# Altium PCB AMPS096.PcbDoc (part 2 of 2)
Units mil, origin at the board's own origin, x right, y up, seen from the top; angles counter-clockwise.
Board outline 2170 x 3820 mil, 2 copper layers (Top Layer, Bottom Layer), stack 62 mil thick; 82 components, 27 nets, 181 pads, 486 vias.
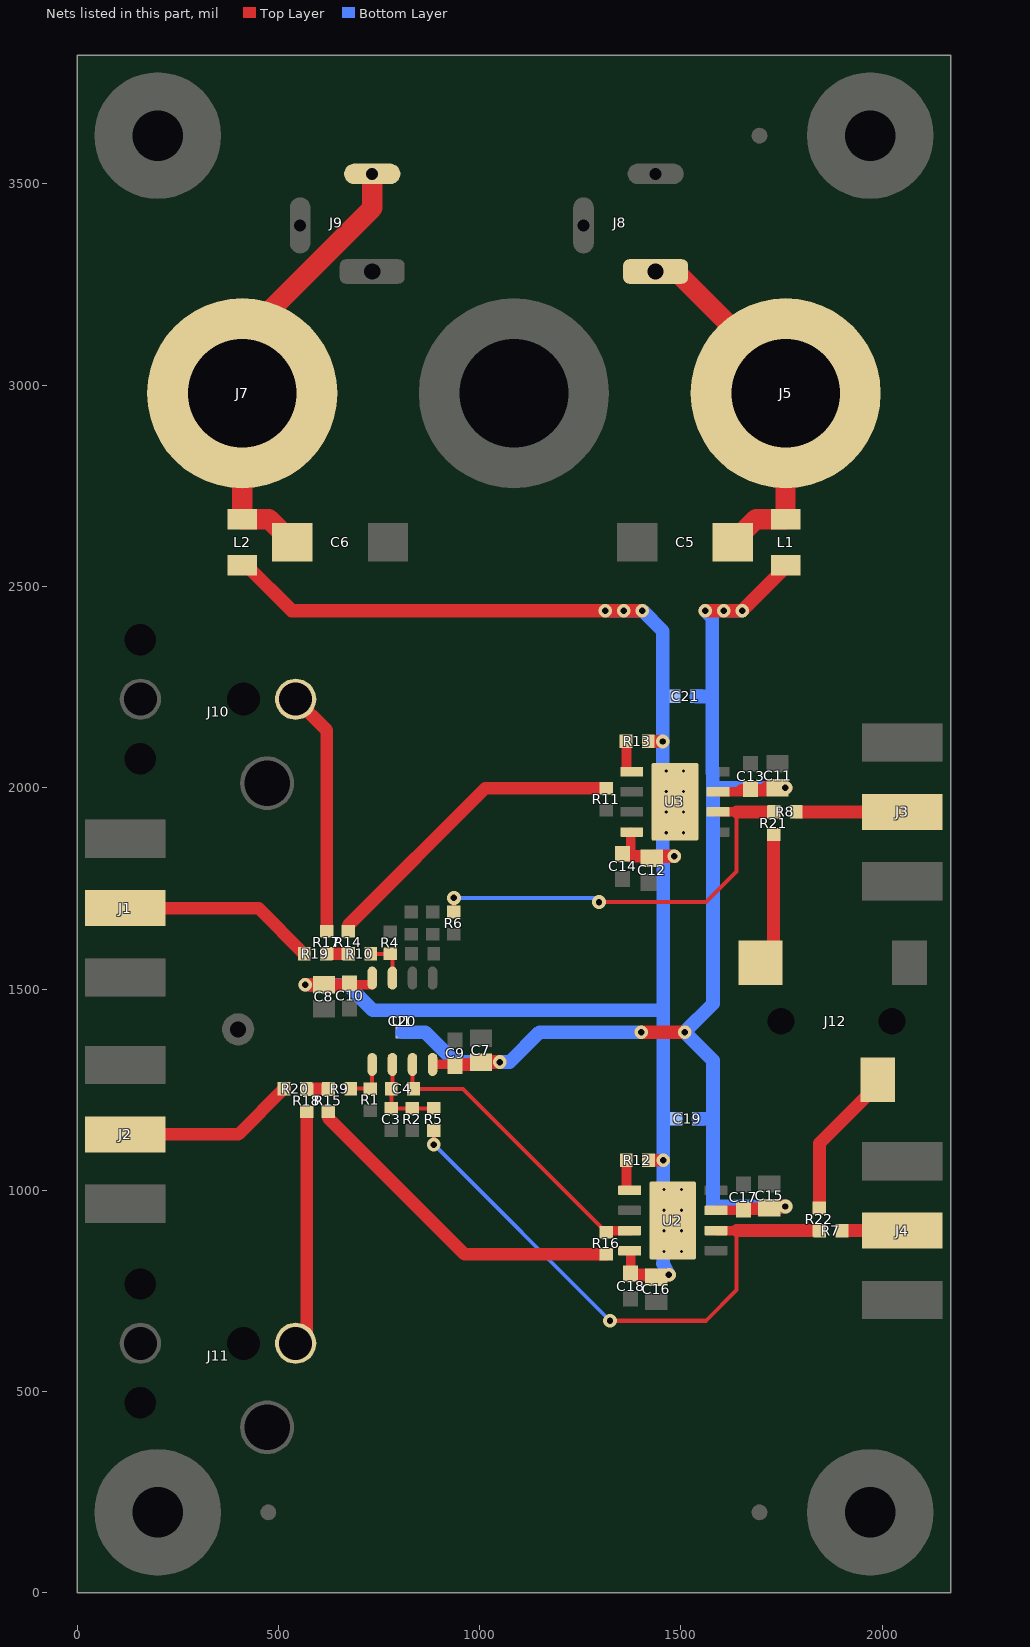
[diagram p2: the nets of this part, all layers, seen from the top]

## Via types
v1: diameter 34, hole 16, Top Layer to Bottom Layer, tented both sides, 470 vias
v2: diameter 19.68, hole 7.87, Top Layer to Bottom Layer, tented both sides, 8 vias
v3: diameter 19.68, hole 7.87, Top Layer to Bottom Layer, 8 vias

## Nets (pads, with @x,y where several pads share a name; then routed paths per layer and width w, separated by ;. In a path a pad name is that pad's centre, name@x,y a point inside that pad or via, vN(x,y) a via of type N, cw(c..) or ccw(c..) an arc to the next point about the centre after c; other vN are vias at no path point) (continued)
NetC3_1: C3.1 C4.1 R2.2 R5.1 U1.6 | length 215.8
  Top Layer w10: U1.6@783,1312.72 783,1254.56 C4.1@780.44,1252 C3.1@780.44,1203.56 R5.1@886,1203.56
NetC4_2: C4.2 R16.2 U1.7 U2.3 | length 750
  Top Layer w10: U1.7@833,1312.72 833,1254.56 C4.2@835.56,1252 958.06,1252 R16.2@1314,896.06
  Top Layer w23.62: R16.2@1314,896.06 1317.94,900 U2.3@1374.72,900
NetC5_1: C5.1 J5.1 J8.1 L1.1 | length 933.3
  Top Layer w50: J8.1@1437,3282.43 1487.57,3282.43 1760,3010 J5.1@1760,2980 L1.1@1760,2667.09 1686.18,2667.09 C5.1@1629.09,2610
NetC6_2: C6.2 J7.1 J9.2 L2.1 | length 1139.2
  Top Layer w50: C6.2@533.94,2610 476.85,2667.09 L2.1@410,2667.09 J7.1@410,2980 410,3117 733,3440 J9.2@733,3524.95
NetJ1_1: J1.1 R19.2 | length 491
  Top Layer w31.5: J1.1@120,1701 450.41,1701 R19.2@563.97,1587.44
NetJ2_1: J2.1 R20.2 | length 441
  Top Layer w31.5: J2.1@120,1139 400.41,1139 R20.2@513.97,1252.56
NetJ3_1: J3.1 R8.1 | length 264
  Top Layer w31.5: R8.1@1786.03,1940 J3.1@2050,1940
NetJ4_1: J4.1 R7.1 | length 150
  Top Layer w31.5: R7.1@1900.03,900 J4.1@2050,900
NetJ10_3: J10.3 R17.1 | length 608.5
  Top Layer w31.5: J10.3@542.83,2220 620,2142.83 R17.1@620,1643.47
NetJ11_3: J11.3 R18.2 | length 586.2
  Top Layer w31.5: J11.3@542.83,620 570,647.17 R18.2@570,1194.97
NetJ12_2: J12.2 R21.2 | length 323.5
  Top Layer w31.5: J12.2@1697.56,1565.67 J12.2@1710,1578.11 ; J12.2@1730,1578.11 R21.2@1730,1883.97
NetJ12_3: J12.3 R22.1 | length 378.3
  Top Layer w31.5: R22.1@1844,956.03 1844,1117 1988.9,1261.9 J12.3@1988.9,1274.33
NetR1_2: R1.2 R9.1 U1.5 | length 110.7
  Top Layer w10: R9.1@679.56,1252.56 R1.2@728,1252.56 733,1257.56 U1.5@733,1312.72
NetR4_1: R4.1 R10.1 U1.3 | length 110.7
  Top Layer w10: R10.1@729.56,1587.44 R4.1@778,1587.44 783,1582.44 U1.3@783,1527.28
NetR5_2: R5.2 R7.2 R22.2 U2.6 | length 1392.4
  Top Layer w10: v1(886,1113.72) R5.2@886,1148.44 ; v1(1323.72,676.01) 1562.16,676.01 1638.15,752 1638.15,900
  Top Layer w23.62: U2.6@1589.28,900 1638.15,900
  Top Layer w31.5: 1638.15,900 R7.2@1834,900
  Bottom Layer w10: v1(886,1113.72) v1(1323.72,676.01)
NetR6_2: R6.2 R8.2 R21.1 U3.6 | length 1061.3
  Top Layer w10: R6.2@936,1691.56 v1(936,1726.28) ; v1(1296.27,1716.01) 1562.16,1716.01 1638.15,1792 1638.15,1940
  Top Layer w23.62: U3.6@1589.28,1940 1638.15,1940
  Top Layer w31.5: 1638.15,1940 R8.2@1730,1940
  Bottom Layer w10: v1(936,1726.28) 1286,1726.28 v1(1296.27,1716.01)
NetR9_2: R9.2 R15.2 R18.1 R20.1 | length 55.4
  Top Layer w31.5: R20.1@569.09,1252.56 R9.2@624.44,1252.56
NetR10_2: R10.2 R14.2 R17.2 R19.1 | length 55.4
  Top Layer w31.5: R19.1@619.09,1587.44 R10.2@674.44,1587.44
NetR11_1: R11.1 R14.1 | length 796.6
  Top Layer w31.5: R14.1@673.53,1643.47 673.53,1658.53 1014.06,1999.06 R11.1@1314,1999.06
NetR12_2: R12.2 U2.1 | length 63
  Top Layer w10: U2.1@1365.17,1009.55 U2.1@1374.72,1000
  Top Layer w25: U2.1@1365.17,1009.55 R12.2@1365.17,1059
NetR13_2: R13.2 U3.1 | length 63
  Top Layer w10: U3.1@1365.17,2049.55 U3.1@1374.72,2040
  Top Layer w25: U3.1@1365.17,2049.55 R13.2@1365.17,2099
NetR15_1: R15.1 R16.1 | length 845.7
  Top Layer w31.5: R15.1@623.53,1194.97 623.53,1180.35 962.94,840.94 R16.1@1314,840.94
VS+: C7.1 C9.1 C11.1 C13.1 C15.1 C17.1 C19.1 C20.1 C21.1 L1.2 U1.8 U2.7 U3.7 | length 3599
  Top Layer w23.62: U1.8@883,1312.72 C9.1@939,1312.72 ; U2.7@1589.28,950 1646.06,950 C17.1@1650,953.94 ; U3.7@1589.28,1990 1646.06,1990 1650,1993.94
  Top Layer w31.5: C9.1@939,1312.72 996.09,1312.72 C7.1@1002,1318.62 ; C17.1@1650,953.94 1707.09,953.94 C15.1@1713,959.84 ; 1650,1993.94 1707.09,1993.94 C11.1@1713,1999.84
  Top Layer w34: C7.1@1003,1318.62 v1(1049.53,1318.62) ; v1(1401,1393) v1(1509,1393) ; v1(1560,2440) v1(1606,2440) v1(1651.91,2440) ; v1@1652.09,2440 L1.2@1760,2547.91 ; C15.1@1713,959.84 v1(1759.53,959.84) ; C11.1@1713,1999.84 v1(1759.53,1999.84)
  Bottom Layer w34: C20.1@808,1393 864.25,1393 938.63,1318.62 v1(1049.53,1318.62) 1074.42,1318.62 1148.8,1393 v1(1401,1393) ; C21.1@1538.47,2226.92 1575.37,2226.92 1577.29,2225 ; C19.1@1542.56,1177.76 1577.26,1177.76 1579.5,1180 ; v1(1651.91,2440) v1(1606,2440) v1(1560,2440) 1577.29,2422.71 1577.29,2225 ; v1(1759.53,959.84) 1579.5,959.84 1579.5,1180 ; v1(1759.53,1999.84) 1579.5,1999.84 ; 1577.29,2225 1577.29,2068.13 1579.5,1999.84 ; 1579.5,1180 1579.5,1322.5 v1(1509,1393) 1579.5,1463.5 1579.5,1999.84
VS-: C8.1 C10.1 C12.1 C14.1 C16.1 C18.1 C19.2 C20.2 C21.2 L2.2 R12.1 R13.1 U1.4 U2.4 U2.9@1479.73,925 U3.4 U3.9@1484.95,1965 | length 4287.5
  Top Layer w23.62: C10.1@677,1510.55 U1.4@733,1510.55 ; C18.1@1374.72,789.56 U2.4@1374.72,850 ; 1374.72,1829.56 U3.4@1374.72,1890
  Top Layer w31.5: C8.1@613,1510.55 C10.1@677,1510.55 ; C18.1@1374.72,789.56 C16.1@1437,789.56 ; 1374.72,1829.56 C12.1@1437,1829.56 ; R12.1@1419.74,1075 v1(1456.03,1075) ; 1436.28,2115 v1(1455,2115)
  Top Layer w34: L2.2@420,2552.91 532.91,2440 v1(1404,2440) ; v1(566.47,1510.55) C8.1@613,1510.55 ; C12.1@1437,1829.56 v1(1483.53,1829.56) ; C16.1@1438.58,783.59 v1(1470.08,790)
  Bottom Layer w34: v1(566.47,1510.55) 671.2,1510.55 734.75,1447 808,1447 1455,1447 ; v1(1312.09,2440) v1(1358,2440) v1(1404,2440) 1455,2389 1455,2099 1455,1829.56 ; v1(1470.08,790) 1455,818.09 1456.03,819.12 v1(1456.03,1075) 1456.03,1828.53 1455,1829.56 ; v1(1483.53,1829.56) 1455,1829.56
  other v2: 1458.08,848.23 1501.39,848.23 1458.08,1001.77 1501.39,1001.77 1463.3,1888.23 1506.61,1888.23 1463.3,2041.77 1506.61,2041.77
  other v3: 1458.08,899.41 1501.39,899.41 1458.08,950.59 1501.39,950.59 1463.3,1939.41 1506.61,1939.41 1463.3,1990.59 1506.61,1990.59
pads on no net: FID1.1 FID2.1 FID3.1 FID4.1 FID5.1 FID6.1 H5.0 H6.0 H7.0 H8.0 J8.3 J9.3 J10.4 J10.M1 J10.M2 J10.M3 J11.4 J11.M1 J11.M2 J11.M3 J12.4 J12.5 U2.2 U2.5 U2.8 U2.9@1479.73,925 U3.2 U3.5 U3.8 U3.9@1484.95,1965

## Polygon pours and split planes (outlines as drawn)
GND on Top Layer "TOP_LAYER_GND_P006" (solid, remove dead copper, pour order 6): 25,3795 2145,3795 2145,25 25,25
VS- on Bottom Layer "BOTTOM_LAYER_VS-_P020" (solid, remove dead copper, pour order 20): 1420,2061.68 1424.95,2056.72 1424.95,1868.68 1545,1868.68 1545,2061.68
GND on Bottom Layer "BOTTOM_LAYER_GND_P016" (solid, remove dead copper, pour order 16): 30,3790 25.49,3785.49 25.49,25.49 2144.51,25.49 2144.51,3794.51 25.49,3794.51 25,3795
VS- on Bottom Layer "BOTTOM_LAYER_VS-_P014" (solid, remove dead copper, pour order 14): 1419.73,1021.68 1419.73,828.68 1535,828.68 1535,1021.68

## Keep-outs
Keep-Out Layer:
  text ".Layer_Name" at 567,-858.49 h60

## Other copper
Top Layer:
  text ".Layer_Name" at 567,-858.49 h60
Bottom Layer:
  text ".Layer_Name" at 567,-858.49 h60

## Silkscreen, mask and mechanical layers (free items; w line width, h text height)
Top Overlay:
  text "Warning" at 965,3735 h72.83
  text "Connectors" at 925,3640 h72.83
  text "are positive" at 920,3540 h72.83
  text "tip" at 1050,3435 h72.83
  text "'.PRJ_Number'.PCB_Rev" at 688.05,331 h40
  text "BUF634ADDAEVM" at 1133.97,330 h72.83
  text ".Layer_Name" at 567,-858.49 h60
Bottom Overlay:
  text ".Layer_Name" at 567,-858.49 h60
Top Paste:
  text ".Layer_Name" at 567,-858.49 h60
Bottom Paste:
  text ".Layer_Name" at 567,-858.49 h60
Top Solder:
  text ".Layer_Name" at 567,-858.49 h60
  text ".Layer_Name" at 567,-858.49 h60
Bottom Solder:
  text ".Layer_Name" at 567,-858.49 h60
Drill Guide:
  text ".Layer_Name" at 567,-858.49 h60
M1 Board Outline:
  the board outline again, w10
  text ".Layer_Name" at 567,-858.49 h60
M2 Board Dimensions:
  rectangle: -10,-265 115,-140
  rectangle: 115,-390 490,-265
  lines w7: -10,-265 990,-265 ; 115,-390 115,-140 ; 240,-390 240,-140 ; 490,-390 490,-140 ; 740,-390 740,-140 ; -10,-390 990,-390 990,-140 -10,-140 -10,-390
  text ".Layer_Name" at 567,-858.49 h60
M3 3D STEP Top:
  text ".Layer_Name" at 567,-858.49 h60
M4 3D STEP Bottom:
  text ".Layer_Name" at 567,-858.49 h60
M5 Assembly Top:
  lines w10: -302,-930.17 6298,-930.17 ; -302,-726.83 6300,-726.83 ; -302,-523.5 -302,-1133.5 3703,-1133.5 6300,-1133.5 6300,-523.5 -301.5,-523.5 -301.5,-1133.5 1274,-1133.5 ; 2163,-1133.5 2163,-523.5 ; 3430,-726.83 3430,-523.5 ; 4270,-726.83 4270,-523.5 ; 4892,-1140 4892,-937.17
  text "COMPONENTS MARKED 'DNP' SHOULD NOT BE POPULATED." at 1143.5,-318.5 h60
  text "ASSEMBLY VARIANT:" at 1143,-434 h60
  text ".VariantName" at 2179,-434 h60
  text "BUF634ADEVM" at 2737,-649 h60
  text "PCB VIEWED FROM TOP SIDE" at -238.5,-655.67 h60
  text "BOARD #:" at 2238,-655.67 h60
  text "REV:" at 3628,-655.67 h60
  text ".PCB_Rev" at 3919.5,-655.67 h60
  text "SVN REV:" at 4466,-655.67 h60
  text ".VersionControl_RevNumber" at 4972,-655.67 h60
  text "TID #:" at 2238,-859 h60
  text ".TID" at 2783.5,-859 h60
  text "PLOT NAME =" at -238.5,-1064.34 h60
  text ".plot_File_Name" at 567,-1064.34 h60
  text "GENERATED    :" at 2240,-1064.34 h60
  text ".Print_Date" at 3109.5,-1064.34 h60
  text ".Print_Time" at 3838.5,-1064.34 h60
  text "TEXAS INSTRUMENTS" at 5103,-1064.34 h60
M6 Assembly Bottom:
  lines w10: -302.5,-727.33 6299.5,-727.33 ; -300.5,-930.67 6299.5,-930.67 ; 1105.5,-1140.5 1105.5,-937.67 ; 1727.5,-727.33 1727.5,-524 ; 2567.5,-727.33 2567.5,-524 ; 3834.5,-1134 3834.5,-524 ; 4723.5,-1134 6299,-1134 6299,-524 -302.5,-524 -302.5,-1134 2294.5,-1134 6299.5,-1134 6299.5,-524
  text "COMPONENTS MARKED 'DNP' SHOULD NOT BE POPULATED." at 6092,-318 h60
  text ".VariantName" at 5048,-434 h60
  text "ASSEMBLY VARIANT:" at 6087,-434 h60
  text ".VersionControl_RevNumber" at 1025.5,-656.17 h60
  text "SVN REV:" at 1531.5,-656.17 h60
  text ".PCB_Rev" at 2078,-656.17 h60
  text "REV:" at 2369.5,-656.17 h60
  text ".PRJ_Number" at 3214,-656.17 h60
  text "BOARD #:" at 3759.5,-656.17 h60
  text "PCB VIEWED FROM BOTTOM SIDE" at 6236,-656.17 h60
  text ".TID" at 3214,-859.5 h60
  text "TID #:" at 3759.5,-859.5 h60
  text "TEXAS INSTRUMENTS" at 894.5,-1064.84 h60
  text ".Print_Time" at 2159,-1064.84 h60
  text ".Print_Date" at 2888,-1064.84 h60
  text "GENERATED    :" at 3757.5,-1064.84 h60
  text ".plot_File_Name" at 5430.5,-1064.84 h60
  text "PLOT NAME =" at 6236,-1064.84 h60
M9 Title Sheet:
  drawing of 57 lines, arcs and shapes, not listed
  text "1" at 729.84,8036.5 h70
  text "2" at 3225.5,8036.5 h70
  text "3" at 5714.84,8036.5 h70
  text "4" at 8221.51,8036.5 h70
  text "5" at 10720.5,8036.5 h70
  text "6" at 13225.5,8036.5 h70
  text "A" at -426.5,6893.5 h70
  text "A" at 14373.5,6893.5 h70
  text "B" at -426.5,4513.5 h70
  text "B" at 14373.5,4513.5 h70
  text "C" at -426.5,2138.5 h70
  text "C" at 14373.5,2138.5 h70
  text "PROJECT TITLE:" at 11333.5,277.5 h45
  text ".PRJ_Title" at 11383.5,144.17 h70
  text "DESIGNED FOR:" at 11333.5,-23.5 h45
  text ".PRJ_Customer" at 11383.5,-163.5 h70
  text "D" at -426.5,-231.5 h70
  text "D" at 14373.5,-231.5 h70
  text "FILE NAME:" at 11333.5,-323.5 h45
  text ".PCB_File_Name_No_Path" at 11383.5,-443.5 h70
  text "Texas Instruments (TI) and/or its licensors do not warrant the accuracy or completeness of this specification" at 6364,-605.34 h45
  text "ENGINEER:" at 11333.5,-613.5 h45
  text "LAYOUT BY:" at 12838.5,-613.5 h45
  text "or any information contained therein. TI and/or its licensors do not warrant that this design will meet" at 6319.01,-718 h45
  text "Sean Cashin" at 11383.5,-768.49 h70
  text "Sean Cashin" at 12889,-768.49 h70
  text "the specifications, will be suitable for your application or fit for any particular purpose, or will operate in" at 6319.01,-830.67 h45
  text ".Layer_Name" at 567,-858.49 h60
  text "ALTIUM DESIGNER VERSION:" at 12838.5,-923.5 h45
  text "an implementation. TI and/or its licensors do not warrant that the design is production worthy. You should" at 6319.01,-943.33 h45
  text "completely validate and test your design implementation to confirm the system functionality for your application." at 6364,-1056 h45
  text ".print_Scale" at 11383.5,-1056.83 h70
  text ".Application_BuildNumber" at 12889,-1056.83 h70
  text "1" at 729.84,-1263.5 h70
  text "2" at 3225.5,-1263.5 h70
  text "3" at 5714.84,-1263.5 h70
  text "4" at 8221.51,-1263.5 h70
  text "5" at 10720.5,-1263.5 h70
  text "6" at 13225.5,-1263.5 h70
M10 Fab Notes:
  drawing of 189 lines, arcs and shapes, not listed
  text "DESIGN INFORMATION" at 12382.02,6356.17 h60
  text "MIN. TRACK WIDTH:" at 11737.46,6224.05 h60
  text "8" at 12833.7,6224.05 h60
  text "MIL" at 12988.46,6224.05 h60
  text "MIN. CLEARANCE:" at 11737.46,6099.92 h60
  text "0.2" at 12773.7,6099.93 h60
  text "mm" at 12988.46,6099.92 h60
  text "MIN. VIA PAD SIZE:" at 11737.46,5975.8 h60
  text "24" at 12803.71,5975.8 h60
  text "MIL" at 12988.46,5975.8 h60
  text "0.05mm (2MIL)" at 12432.46,5845.9 h60
  text "MINIMUM ANNULAR RING" at 11408.23,5837.67 h60
  text "EXTERNAL" at 13140.46,5837.67 h60
  text "PER" at 11608.23,5727.55 h60
  text "IPC-D-275 CLASS 2 LEVEL C" at 11828.23,5727.54 h60
  text "MIL, HOLES" at 13316.46,5627.07 h60
  text "+/-" at 12924,5618.48 h60
  text "+/-" at 13778,5618.48 h60
  text "REGISTRATION TOLERANCES:" at 11408.23,5617.42 h60
  text "METAL" at 12608,5617.42 h60
  text "5" at 13184.2,5617.42 h60
  text "3" at 14017.2,5617.42 h60
  text "MIL" at 14133.46,5617.42 h60
  text "HOLE SIZE TOLERANCE (UNLESS OTHERWISE SPECIFIED):" at 11408.23,5519.1 h60
  text "+/-" at 13778,5516.23 h60
  text "3" at 14017.2,5515.17 h60
  text "MIL" at 14133.46,5515.17 h60
  text "MATERIAL:" at 11333.46,5377.52 h60
  text "FR-4 High Tg" at 12319.9,5249 h60
  text "X" at 12175.46,5241.01 h60
  text "FR-408" at 11754.46,5236.49 h60
  text "OTHER" at 13242.46,5236.49 h60
  text "62 MIL (1.6mm) +/-10%" at 12074.56,5093.46 h60
  text "X" at 11954.46,5091.01 h60
  text "THICKNESS:" at 11408.23,5085.24 h60
  text "OTHER" at 13359.46,5085.24 h60
  text "TOLERANCE:" at 11408.23,4946.92 h60
  text "X" at 12256.46,4946.92 h60
  text "ANSI IPC-6012 TYPE 3 CLASS 2" at 12434.48,4946.92 h60
  text "OTHER +/-" at 12434.46,4802.73 h60
  text "BOW & TWIST:" at 11408.23,4657.54 h60
  text "X" at 12256.46,4657.54 h60
  text "ANSI IPC-6012 TYPE 3 CLASS 2" at 12434.48,4657.54 h60
  text "OTHER +/-" at 12434.46,4510.85 h60
  text "DRILLING:" at 11333.46,4380.23 h60
  text "NC_DRILL FILES" at 13094.46,4275.04 h60
  text "REFERENCE:" at 11408.23,4271.1 h60
  text "X" at 12065.46,4271.01 h60
  text "AS SHOWN" at 12243.46,4271.1 h60
  text "X" at 12966.46,4271.1 h60
  text "OTHER" at 13392.46,4128.85 h60
  text "PTH COPPER THICKNESS:" at 11407.91,4125.32 h60
  text "X" at 12547.14,4125.32 h60
  text "20-30 um" at 12675.14,4125.32 h60
  text "BOARD FINISH:" at 11333.46,3977.73 h60
  text "SILKSCREEN:" at 11488.68,3867.6 h60
  text "X" at 12446.46,3867.6 h60
  text "TOP" at 12563.46,3867.6 h60
  text "X" at 12956.46,3867.6 h60
  text "BOTTOM" at 13074.46,3867.6 h60
  text "SILKSCREEN COLOR:" at 11488.68,3712.41 h60
  text "X" at 12445.46,3712.41 h60
  text "WHITE" at 12563.46,3712.41 h60
  text "OTHER" at 13074.46,3712.41 h60
  text "X" at 12576.46,3568.96 h60
  text "GREEN" at 12694.46,3568.96 h60
  text "OTHER" at 13312.46,3568.96 h60
  text "SOLDER RESIST COLOR:" at 11488.68,3562.1 h60
  text "X" at 12576.46,3414.71 h60
  text "MATTE" at 12694.46,3414.71 h60
  text "SEMI-GLOSS" at 13312,3414.07 h60
  text "IMMERSION GOLD (ENIG)" at 12394.46,3241.94 h60
  text "ENEPIG" at 13732,3234.72 h60
  text "SURFACE FINISH:" at 11333.46,3233.72 h60
  text "X" at 12216.46,3233.72 h60
  text "IMM. TIN/SILVER OR EQUIV" at 11663,3096.4 h60
  text "OTHER" at 13094.46,3092.47 h60
  text "ARRAY/PANEL:" at 11333.46,2937.09 h60
  text "CUT AND TRIM PER M1 BOARD OUTLINE" at 12394.46,2928.87 h60
  text "N.C. ROUTE" at 12394.46,2792.9 h60
  text "X" at 13082.46,2792.9 h60
  text "V. SCORE" at 13260.46,2792.9 h60
  text "CERTIFICATION:" at 11333.46,2663.77 h60
  text "MATERIALS AND WORKMANSHIP FOR ALL PCBS" at 12058.46,2663.77 h60
  text "TO MEET OR EXCEED THE REQUIREMENTS OF:" at 12058.46,2569.71 h60
  text "X" at 11695.97,2441.08 h60
  text "ANSI IPC-A-600F CLASS ->" at 11823.96,2441.08 h60
  text "X" at 13471.97,2441.08 h60
  text "2" at 13581.96,2441.08 h60
  text "1" at 13266.96,2439.58 h60
  text "3" at 13935.96,2439.58 h60
  text "X" at 12507.97,2293.39 h60
  text "RoHS" at 12635.96,2293.39 h60
  text "OTHER" at 13280.36,2293.39 h60
  text "PER ORDER" at 13677.42,2293.39 h60
  text "ALL BOARDS MUST MEET OR EXCEED UL94-V0 REQUIREMENTS." at 11361,2139.57 h60
  text "PCB MUST BEAR THE UL94V-0 UL REGISTERED MATERIAL ID NUMBER" at 11361,2023.5 h60
  text "ADDITIONAL REQUIREMENTS:" at 11333.46,1854.08 h60
  text "MICROSECTION:" at 11408.23,1746.95 h60
  text "YES" at 12313.96,1746.95 h60
  text "REQUIRED" at 13175.46,1602.62 h60
  text "BARE BOARD ELEC. TEST:" at 11408.23,1599.76 h60
  text "NONE" at 12713.96,1599.76 h60
  text "X" at 13057.46,1599.76 h60
  text "PER ORDER" at 13767.46,1599.76 h60
  text "XX MIL VIAS REQUIRE NON-CONDUCTIVE FILL AND PLANARIZE" at 11576.38,1394.82 h59
  text "XX MIL VIAS REQUIRE CONDUCTIVE FILL AND PLANARIZE" at 11584.38,1290.84 h60
  text "OUTER XX MIL TRACES REQUIRE 50 OHM SINGLE-ENDED IMPEDANCE" at 11583.39,1127.46 h58
  text "LAYER 2 & 3 (INNER LAYERS) XX MIL WIDE, XX MIL SPACE / TRACES REQUIRE 100 OHM DIFFERENTIAL IMPEDANCE" at 11575.39,891.74 h60
  text ".Layer_Name" at 567,-858.49 h60
M11 Gerber Information:
  lines w10: -302,-930.17 6298,-930.17 ; -302,-726.83 6300,-726.83 ; -302,-523.5 -302,-1133.5 3703,-1133.5 6300,-1133.5 6300,-523.5 -301.5,-523.5 -301.5,-1133.5 1274,-1133.5 ; 2163,-1133.5 2163,-523.5 ; 3430,-726.83 3430,-523.5 ; 4270,-726.83 4270,-523.5 ; 4892,-1140 4892,-937.17
  text "ALL ARTWORK VIEWED FROM TOP SIDE" at -238.5,-655.67 h60
  text "BOARD #:" at 2238,-655.67 h60
  text ".PRJ_Number" at 2783.5,-655.67 h60
  text "REV:" at 3628,-655.67 h60
  text ".PCB_Rev" at 3919.5,-655.67 h60
  text "SVN REV:" at 4466,-655.67 h60
  text ".VersionControl_RevNumber" at 4972,-655.67 h60
  text "LAYER NAME =" at -238.5,-858.49 h60
  text "TID #:" at 2238,-859 h60
  text ".TID" at 2783.5,-859 h60
  text "PLOT NAME =" at -238.5,-1064.34 h60
  text ".plot_File_Name" at 567,-1064.34 h60
  text "GENERATED    :" at 2240,-1064.34 h60
  text ".Print_Date" at 3109.5,-1064.34 h60
  text ".Print_Time" at 3838.5,-1064.34 h60
  text "TEXAS INSTRUMENTS" at 5103,-1064.34 h60
M12 Stackup:
  drawing of 191 lines, arcs and shapes, not listed
  text "Layer" at 9787.84,7537.5 h60
  text "Name" at 10197.76,7537.5 h60
  text "Material" at 11127.5,7537.5 h60
  text "Thickness" at 11987.27,7537.5 h60
  text "Constant" at 12637.1,7537.5 h60
  text "Board Layer Stack" at 13206.96,7537.5 h60
  text "1" at 9787.84,7417.5 h60
  text "Top Overlay" at 10197.76,7417.5 h60
  text "2" at 9787.84,7297.5 h60
  text "Top Solder" at 10197.76,7297.5 h60
  text "Solder Resist" at 11127.5,7297.5 h60
  text "0.40mil" at 11987.27,7297.5 h60
  text "3.5" at 12637.1,7297.5 h60
  text "3" at 9787.84,7177.5 h60
  text "Top Layer" at 10197.76,7177.5 h60
  text "Copper" at 11127.5,7177.5 h60
  text "1.40mil" at 11987.27,7177.5 h60
  text "4" at 9787.84,7057.5 h60
  text "Dielectric1" at 10197.76,7057.5 h60
  text "FR-4 High Tg" at 11127.5,7057.5 h60
  text "59.20mil" at 11987.27,7057.5 h60
  text "4.8" at 12637.1,7057.5 h60
  text "5" at 9787.84,6937.5 h60
  text "Bottom Layer" at 10197.76,6937.5 h60
  text "Copper" at 11127.5,6937.5 h60
  text "1.40mil" at 11987.27,6937.5 h60
  text "6" at 9787.84,6817.5 h60
  text "Bottom Solder" at 10197.76,6817.5 h60
  text "Solder Resist" at 11127.5,6817.5 h60
  text "0.40mil" at 11987.27,6817.5 h60
  text "3.5" at 12637.1,6817.5 h60
  text "7" at 9787.84,6697.5 h60
  text "Bottom Overlay" at 10197.76,6697.5 h60
  text ".Layer_Name" at 567,-858.49 h60
M13 Component Bodies Top:
  text ".Layer_Name" at 567,-858.49 h60
M14 Component Bodies Bottom:
  text ".Layer_Name" at 567,-858.49 h60
M15 Courtyards Top:
  text ".Layer_Name" at 567,-858.49 h60
M16 Courtyards Bottom:
  text ".Layer_Name" at 567,-858.49 h60
Drill Drawing:
  circle w10: c2833.72,600.8 r16.58
  circle w10: c2833.72,600.8 r27.63
  circle w10: c2833.72,352.16 r27.63
  lines w10: 2806.09,255.47 2861.34,255.47 2833.72,200.22 2806.09,255.47 ; 2806.09,448.86 2861.34,448.86 2861.34,504.11 2806.09,504.11 2806.09,448.86 ; 2806.09,725.12 2833.72,697.5 2861.34,725.12 2833.72,752.75 2806.09,725.12 ; 2806.09,821.82 2806.09,835.63 2819.9,849.44 2806.09,863.26 2806.09,877.07 2819.9,877.07 2833.72,863.26 2847.53,877.07 2861.34,877.07 2861.34,863.26 2847.53,849.44 2861.34,835.63 2861.34,821.82 2847.53,821.82 2833.72,835.63 2819.9,821.82 2806.09,821.82 ; 2806.09,1001.39 2861.34,1001.39 2833.72,946.14 2806.09,1001.39 ; 2806.09,1070.46 2833.72,1084.27 2861.34,1070.46 2847.53,1098.08 2861.34,1125.71 2833.72,1111.9 2806.09,1125.71 2819.9,1098.08 2806.09,1070.46 ; 2806.09,1194.78 2861.34,1194.78 2861.34,1250.03 2806.09,1250.03 2806.09,1194.78 ; 2806.09,1332.91 2819.9,1332.91 2819.9,1319.1 2847.53,1319.1 2847.53,1332.91 2861.34,1332.91 2861.34,1360.54 2847.53,1360.54 2847.53,1374.35 2819.9,1374.35 2819.9,1360.54 2806.09,1360.54 2806.09,1332.91 ; 2806.09,1457.23 2819.9,1457.23 2833.72,1443.42 2847.53,1457.23 2861.34,1457.23 2847.53,1471.04 2861.34,1484.86 2847.53,1484.86 2833.72,1498.67 2819.9,1484.86 2806.09,1484.86 2819.9,1471.04 2806.09,1457.23 ; 2806.09,1581.55 2819.9,1581.55 2833.72,1567.74 2847.53,1581.55 2861.34,1581.55 2847.53,1595.36 2861.34,1609.18 2847.53,1609.18 2833.72,1622.99 2819.9,1609.18 2806.09,1609.18 2819.9,1595.36 2806.09,1581.55 ; 2817.14,459.91 2850.29,459.91 2850.29,493.06 2817.14,493.06 2817.14,459.91 ; 2817.14,990.34 2850.29,990.34 2833.72,957.19 2817.14,990.34 ; 2817.14,1587.08 2825.43,1587.08 2833.72,1578.79 2842.01,1587.08 2850.29,1587.08 2842.01,1595.36 2850.29,1603.65 2842.01,1603.65 2833.72,1611.94 2825.43,1603.65 2817.14,1603.65 2825.43,1595.36 2817.14,1587.08
  lines w12: 2756,162.92 5987.49,162.92 ; 2756,1654.76 5987.49,1654.76 ; 3093.86,38.6 3093.86,1779.08 ; 3425.86,38.6 3425.86,1779.08 ; 4062.43,38.6 4062.43,1779.08 ; 4321.57,38.6 4321.57,1779.08 ; 4696.72,38.6 4696.72,1779.08 ; 5421.05,38.6 5421.05,1779.08 ; 2756,38.6 5987.49,38.6 5987.49,1779.08 2756,1779.08 2756,38.6
  text "Symbol" at 2830.59,1692.06 h72
  text "Quantity" at 3131.16,1692.06 h72
  text "Finished Hole Size" at 3463.16,1692.06 h72
  text "Plated" at 4099.72,1692.06 h72
  text "Hole Type" at 4358.86,1692.06 h72
  text "Drill Layer Pair" at 4734.02,1692.06 h72
  text "Hole Tolerance" at 5458.35,1692.06 h72
  text "16" at 3131.16,1567.74 h60
  text "7.87mil (0.200mm)" at 3463.16,1567.74 h60
  text "PTH" at 4099.72,1567.74 h60
  text "Round" at 4358.86,1567.74 h60
  text "Top Layer - Bottom Layer" at 4734.02,1567.74 h60
  text "470" at 3131.16,1443.42 h60
  text "16.00mil (0.406mm)" at 3463.16,1443.42 h60
  text "PTH" at 4099.72,1443.42 h60
  text "Round" at 4358.86,1443.42 h60
  text "Top Layer - Bottom Layer" at 4734.02,1443.42 h60
  text "4" at 3131.16,1319.1 h60
  text "29.92mil (0.760mm)" at 3463.16,1319.1 h60
  text "PTH" at 4099.72,1319.1 h60
  text "Rectangle" at 4358.86,1319.1 h60
  text "Top Layer - Bottom Layer" at 4734.02,1319.1 h60
  text "1" at 3131.16,1194.78 h60
  text "40.00mil (1.016mm)" at 3463.16,1194.78 h60
  text "PTH" at 4099.72,1194.78 h60
  text "Round" at 4358.86,1194.78 h60
  text "Top Layer - Bottom Layer" at 4734.02,1194.78 h60
  text "2" at 3131.16,1070.46 h60
  text "40.16mil (1.020mm)" at 3463.16,1070.46 h60
  text "PTH" at 4099.72,1070.46 h60
  text "Rectangle" at 4358.86,1070.46 h60
  text "Top Layer - Bottom Layer" at 4734.02,1070.46 h60
  text "2" at 3131.16,946.14 h60
  text "66.93mil (1.700mm)" at 3463.16,946.14 h60
  text "NPTH" at 4099.72,946.14 h60
  text "Round" at 4358.86,946.14 h60
  text "Top Layer - Bottom Layer" at 4734.02,946.14 h60
  text "4" at 3131.16,821.82 h60
  text "77.95mil (1.980mm)" at 3463.16,821.82 h60
  text "NPTH" at 4099.72,821.82 h60
  text "Round" at 4358.86,821.82 h60
  text "Top Layer - Bottom Layer" at 4734.02,821.82 h60
  text "2" at 3131.16,697.5 h60
  text "81.89mil (2.080mm)" at 3463.16,697.5 h60
  text "NPTH" at 4099.72,697.5 h60
  text "Round" at 4358.86,697.5 h60
  text "Top Layer - Bottom Layer" at 4734.02,697.5 h60
  text "4" at 3131.16,573.18 h60
  text "81.89mil (2.080mm)" at 3463.16,573.18 h60
  text "PTH" at 4099.72,573.18 h60
  text "Round" at 4358.86,573.18 h60
  text "Top Layer - Bottom Layer" at 4734.02,573.18 h60
  text "2" at 3131.16,448.86 h60
  text "112.99mil (2.870mm)" at 3463.16,448.86 h60
  text "PTH" at 4099.72,448.86 h60
  text "Round" at 4358.86,448.86 h60
  text "Top Layer - Bottom Layer" at 4734.02,448.86 h60
  text "4" at 3131.16,324.54 h60
  text "125.98mil (3.200mm)" at 3463.16,324.54 h60
  text "PTH" at 4099.72,324.54 h60
  text "Round" at 4358.86,324.54 h60
  text "Top Layer - Bottom Layer" at 4734.02,324.54 h60
  text "3" at 3131.16,200.22 h60
  text "270.00mil (6.858mm)" at 3463.16,200.22 h60
  text "PTH" at 4099.72,200.22 h60
  text "Round" at 4358.86,200.22 h60
  text "Top Layer - Bottom Layer" at 4734.02,200.22 h60
  text "514 Total" at 3131.16,75.9 h60
  text "Slot definitions :" at 2830.59,-11.13 h60
  text "Routed Path Length" at 3281.31,-11.13 h60
  text "= Calculated from tool start centre position to tool end centre position." at 3821.05,-11.13 h60
  text "Hole Length" at 3281.31,-60.85 h60
  text "= Routed Path Length + Tool Size = Slot length as defined in the PCB layout" at 3621.24,-60.85 h60
  text ".Layer_Name" at 567,-858.49 h60
M17 Embedded Cavity:
  text ".Layer_Name" at 567,-858.49 h60
M18 Embedded Assembly:
  text ".Layer_Name" at 567,-858.49 h60
M19 Embedded Keepout:
  text ".Layer_Name" at 567,-858.49 h60

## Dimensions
-10,-390 to 990,-390 on M2 Board Dimensions
0,0 to 0,3820 on M2 Board Dimensions
0,0 to 2170,0 on M2 Board Dimensions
